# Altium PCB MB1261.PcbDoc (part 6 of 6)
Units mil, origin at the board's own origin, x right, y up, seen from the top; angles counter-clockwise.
Board outline 5119.1 x 2638.79 mil, 6 copper layers (TOP, L2_GND, L3_SIG, L4_VCC, L5_GND, BOTTOM), stack 61 mil thick; 336 components, 316 nets, 1358 pads, 871 vias.
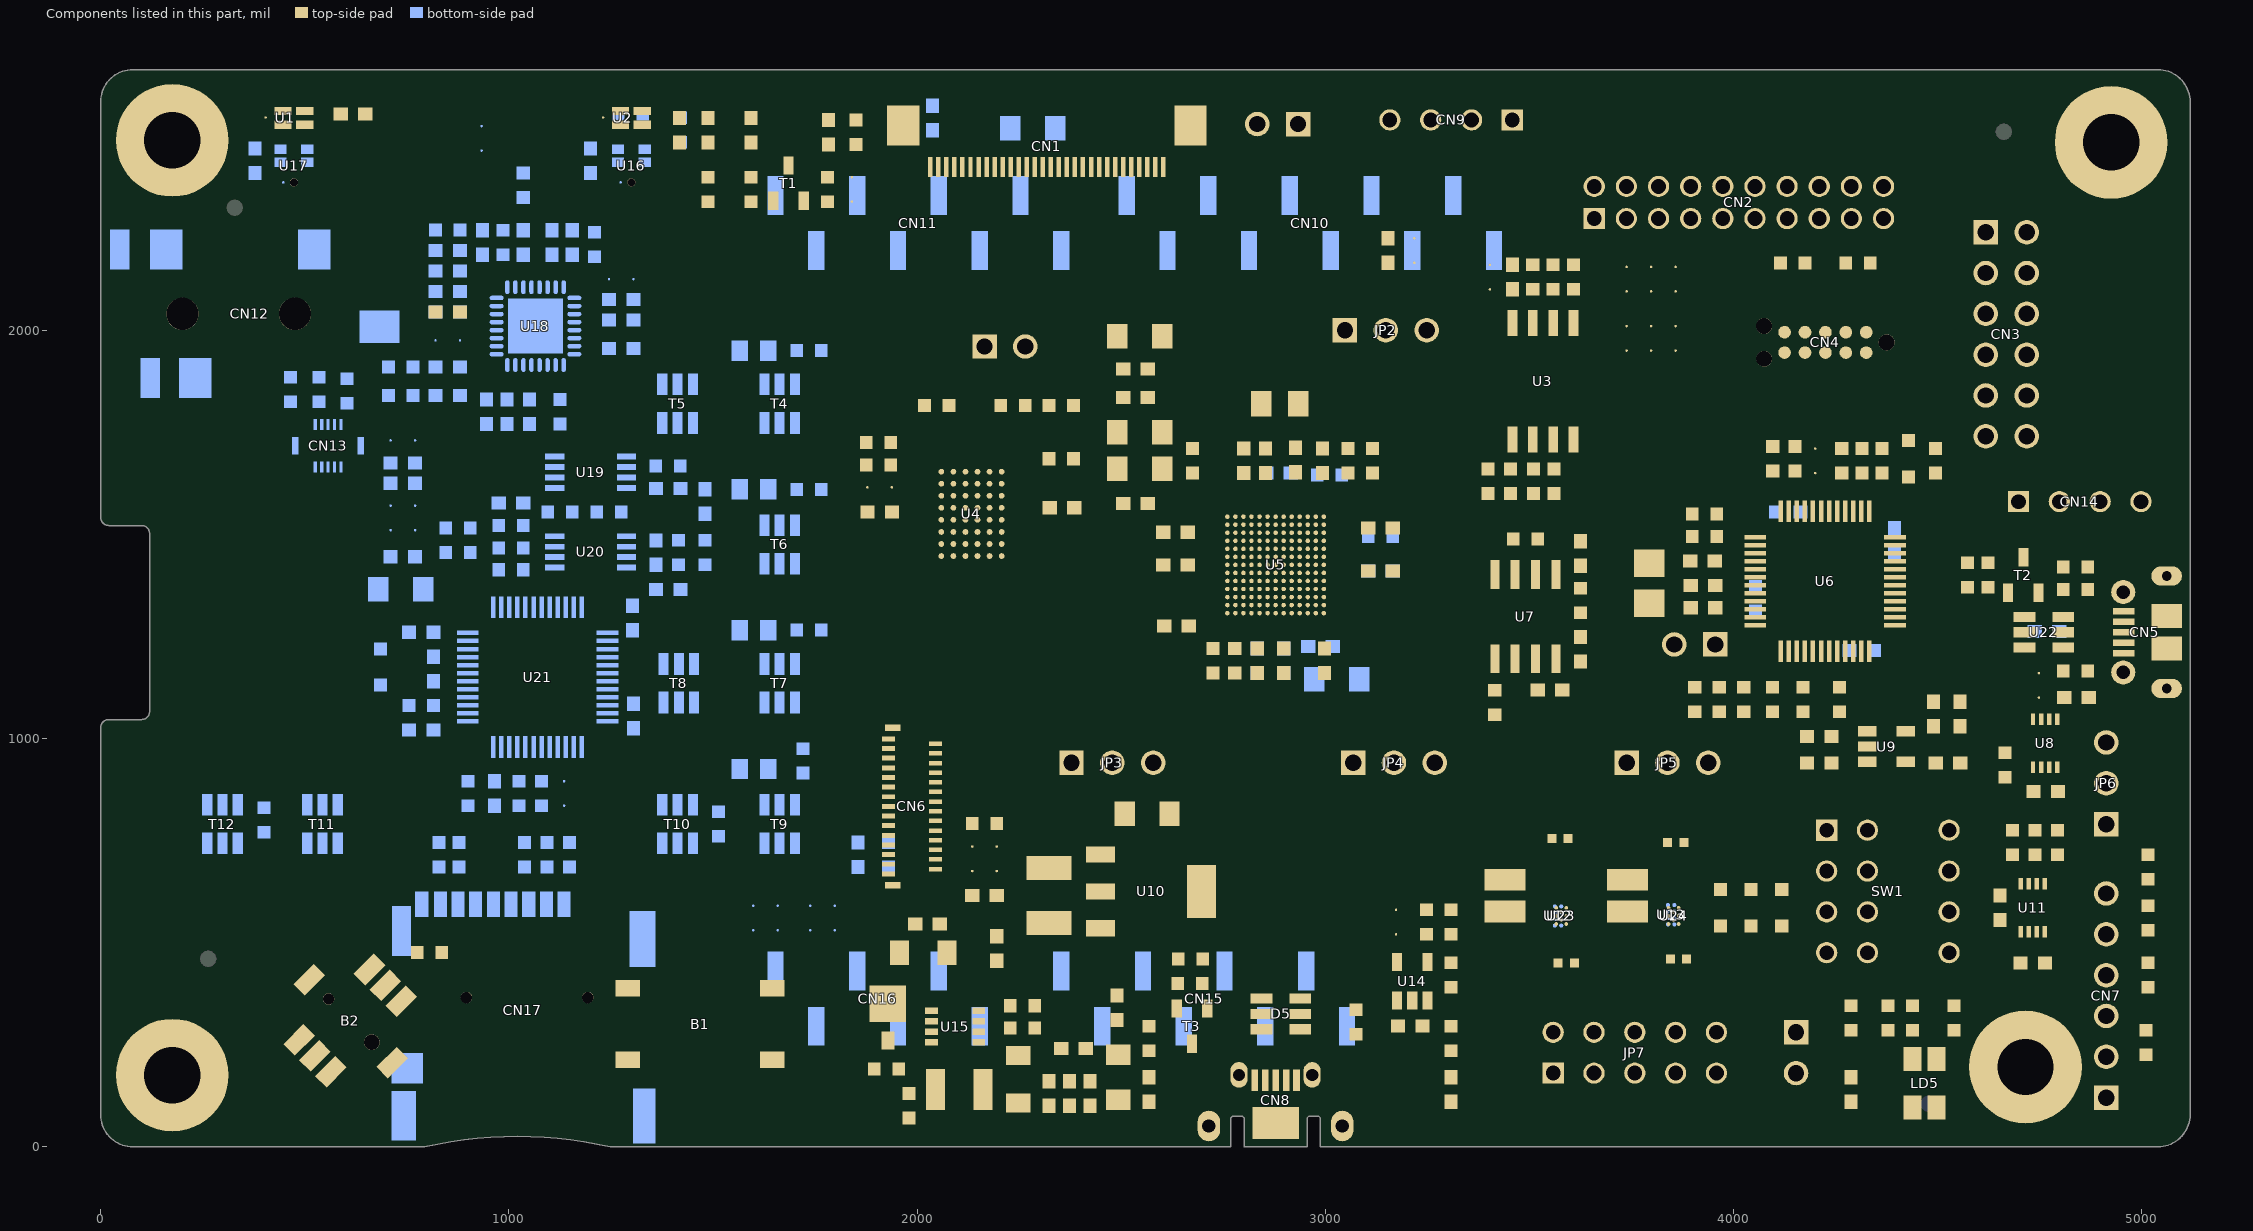
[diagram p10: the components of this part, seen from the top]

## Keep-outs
TOP:
  circle w1: c328.1,2300 r60
  circle w1: c328.1,2300 r65
  circle w1: c4662.1,2486 r60
  circle w1: c4662.1,2486 r65
  circle w1: c263.1,460 r65
  circle w1: c263.1,460 r60
  circle w1: c328.1,2300 r60
  circle w1: c328.1,2300 r65
  circle w1: c4662.1,2486 r60
  circle w1: c4662.1,2486 r65
  circle w1: c263.1,460 r65
  circle w1: c263.1,460 r60
BOTTOM:
  circle w1: c4478.1,105 r65
  circle w1: c4478.1,105 r60
  circle w1: c4662.1,2486 r65
  circle w1: c4662.1,2486 r60
  circle w1: c263.1,460 r60
  circle w1: c263.1,460 r65
  circle w1: c4478.1,105 r65
  circle w1: c4478.1,105 r60
  circle w1: c4662.1,2486 r65
  circle w1: c4662.1,2486 r60
  circle w1: c263.1,460 r60
  circle w1: c263.1,460 r65
Drill Drawing:
  lines w1: 0,78.74 ccw(c78.74,78.74) 78.74,0 ; 0,1025.71 cw(c20,1025.71) 20,1045.71 ; 0,1541.93 ccw(c20,1541.93) 20,1521.93 ; 0,2559.05 cw(c78.74,2559.05) 78.74,2637.79 ; 100,1045.71 ccw(c100,1065.71) 120,1065.71 ; 100,1521.93 cw(c100,1501.93) 120,1501.93 ; 793.1,0 cw(c1020.6,-1007.5) 1248.1,0 ; 5039.36,0 ccw(c5039.36,78.74) 5118.1,78.74 ; 5039.36,2637.79 cw(c5039.36,2559.05) 5118.1,2559.05

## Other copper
TOP:
  region net BLGND: 2124.6,254.63 2124.6,333.37 2113.77,333.37 2113.77,368.8 2098.02,368.8 2098.02,333.37 2088.18,333.37 2088.18,368.8 2072.43,368.8 2072.43,333.37 2061.6,333.37 2061.6,254.63 2072.43,254.63 2072.43,219.2 2088.18,219.2 2088.18,254.63 2098.02,254.63 2098.02,219.2 2113.77,219.2 2113.77,254.63 2124.6,254.63
  text "1" at 1474,106 h35
  text "B" at 1498,29 h35
  text "1" at 2685,-1790 h75
  text "1" at 2685,-1790 h75
  text "PRIMARY SIDE" at 2185,-1940 h60
  text "PRIMARY SIDE" at 2185,-1940 h60
BOTTOM:
  text "6" at 1848,107 h35
  text "6" at 1848,107 h35
  text "B" at 1848,26 h35
  text "B" at 1848,26 h35
  text "6" at 2635,-1790 h75
  text "6" at 2635,-1790 h75
  text "SECONDARY SIDE" at 2185,-1940 h60
  text "SECONDARY SIDE" at 2185,-1940 h60
Multi-Layer:
  pour cut-out: 1378,164 1948,164 1948,3 1378,3

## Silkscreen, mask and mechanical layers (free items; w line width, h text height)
Top Overlay:
  drawing of 5630 lines, arcs and shapes, not listed
  text "STMod+" at 3580,2410 h35 r90
  text "PMOD" at 4610,2340 h35
  text "Camera" at 2095,2305 h35
  text "www.st.com/stm32l4-discovery" at 408,2303 h40
  text "STM32L496G-DISCO" at 423,2162 h80
  text "MB1261B" at 1033.3,2084.3 h50
  text "IDD" at 2975,1900 h35
  text "VDD" at 3215,1900 h35
  text "TAG" at 3960,1855 h35 r90
  text "USB" at 4898.9,1493 h35
  text "STLINK" at 4895,1445 h35
  text "LCD" at 1919.59,1128.45 h35
  text "ARD_5V_OUT" at 2380,995 h35 r90
  text "ARD_5V_IN" at 2560,995 h35 r90
  text "VDD_SWD" at 5105,875 h35 r90
  text "+3V3" at 3645,845 h35
  text "+1V8" at 3885,840 h35
  text "+3V3" at 2985,835 h35
  text "VDD_MCU" at 3235,835 h35
  text "VDD_MCU" at 5105,635 h35 r90
  text "U" at 690,470 h50
  text "L" at 342,283 h50
  text "R" at 843,282 h50
  text "OTG FS" at 3049.1,133.9 h35
  text "D" at 480,115 h50
  text "S" at 1402,107 h35
  text "S" at 1402,107 h35
  text "COM" at 4380,80 h35 r90
  text "RESET" at 1133,49 h50
  text "JOYSTICK" at 390,45 h50
  text "B" at 1402,26 h35
  text "B" at 1402,26 h35
  text "SWD" at 5040,25 h35 r90
  text "E5V" at 3680,15 h35 r90
  text "U5V" at 3790,15 h35 r90
  text "ARD" at 3880,15 h35 r90
  text "STLK" at 3590,0 h35 r90
  text "CHGR" at 3980,0 h35 r90
  text "SILKSCREEN, (PRIMARY)" at 2185,-1940 h60
  text "SILKSCREEN, (PRIMARY)" at 2185,-1940 h60
Bottom Overlay:
  drawing of 467 lines, arcs and shapes, not listed
  text "D12" at 2855,2405 h35 r225
  text "GND" at 3045,2395 h35 r225
  text "D14" at 3250,2395 h35 r225
  text "D0" at 1635,2385 h35 r270
  text "D1" at 1735,2385 h35 r270
  text "D2" at 1835,2385 h35 r270
  text "D4" at 2035,2385 h35 r270
  text "D5" at 2130,2385 h35 r270
  text "D6" at 2235,2385 h35 r270
  text "D7" at 2340,2385 h35 r270
  text "D8" at 2495,2385 h35 r270
  text "D9" at 2595,2385 h35 r270
  text "D10" at 2695,2385 h35 r270
  text "D11" at 2800,2385 h35 r270
  text "D13" at 2985,2385 h35 r270
  text "D3" at 1944,2383 h35 r270
  text "D15" at 3390,2370 h35 r270
  text "AVDD" at 3190,2330 h35 r270
  text "Rev.B" at 3781,1925 h40 r270
  text "Audio Jack" at 340,1745 h35
  text "CTP" at 428.1,1615 h35
  text "MB1261" at 3776,1590 h50 r270
  text "GND" at 4830,1460 h35 r225
  text "+3V3" at 4588,1430 h35 r225
  text "SWDIO" at 4895,1415 h35 r225
  text "SWCLK" at 4680,1410 h35 r225
  text "SWO" at 5070,606 h35
  text "NRST" at 5097,499 h35
  text "SWDIO" at 5117,394 h35
  text "GND" at 5069,303 h35
  text "SWCLK" at 5120,198 h35
  text "5V" at 2635,180 h35 r270
  text "A5" at 1635,175 h35 r270
  text "A4" at 1730,175 h35 r270
  text "A3" at 1830,175 h35 r270
  text "A2" at 1935,175 h35 r270
  text "A1" at 2035,175 h35 r270
  text "A0" at 2130,175 h35 r270
  text "GND" at 2435,145 h35 r270
  text "GND" at 2535,145 h35 r270
  text "VIN" at 2330,140 h35 r270
  text "3V3" at 2720,140 h35 r270
  text "NRST" at 2843,120 h35 r270
  text "B" at 1919,106 h35
  text "B" at 1919,106 h35
  text "VDD" at 5070,98 h35
  text "IOREF" at 2900,90 h35 r270
  text "uSD" at 1400,36.9 h35 r270
  text "B" at 1919,25 h35
  text "B" at 1919,25 h35
  text "E5V" at 3645,15 h35 r270
  text "U5V" at 3752,15 h35 r270
  text "ARD" at 3845,15 h35 r270
  text "STLK" at 3555,0 h35 r270
  text "CHGR" at 3945,0 h35 r270
  text "SILKSCREEN, (SECONDARY)" at 3292,-1944 h60
  text "SILKSCREEN, (SECONDARY)" at 3292,-1944 h60
Top Paste:
  pour cut-out: 2124.6,254.63 2124.6,333.37 2113.77,333.37 2113.77,368.8 2098.02,368.8 2098.02,333.37 2088.18,333.37 2088.18,368.8 2072.43,368.8 2072.43,333.37 2061.6,333.37 2061.6,254.63 2072.43,254.63 2072.43,219.2 2088.18,219.2 2088.18,254.63 2098.02,254.63 2098.02,219.2 2113.77,219.2 2113.77,254.63 2124.6,254.63
  text "SOLDER PASTE (PRIMARY)" at 2185,-1940 h60
  text "SOLDER PASTE (PRIMARY)" at 2185,-1940 h60
Bottom Paste:
  text "SOLDER PASTE (SECONDARY)" at 2185,-1940 h60
  text "SOLDER PASTE (SECONDARY)" at 2185,-1940 h60
Top Solder:
  region: 1378,164 1948,164 1948,3 1378,3
  text "SOLDER MASK (PRIMARY)" at 2185,-1940 h60
  text "SOLDER MASK (PRIMARY)" at 2185,-1940 h60
Bottom Solder:
  text "SOLDER MASK (SECONDARY)" at 2185,-1940 h60
  text "SOLDER MASK (SECONDARY)" at 2185,-1940 h60
Mechanical 1:
  lines w1: 533.63,1615 582.03,1615 582.03,1671.2 533.63,1671.2 533.63,1615 ; 2005,1390 2260,1390 2260,1710 2005,1710 2005,1390 ; 2617.1,1305.4 2647.5,1275 2735,1275 2809.4,1275 2814.5,1269.9 2814.5,1223.8 2829.8,1208.5 2965.4,1208.5 2984,1227.1 2984,1269 2990,1275 3030,1275 3030,1320.1 3035.1,1325.2 3126.3,1325.2 3132,1330.9 3132,1512.7 3095.4,1549.3 3030,1549.3 3030,1570 2972,1570 2969.1,1572.9 2969.1,1593.3 2955.5,1606.9 2790.2,1606.9 2778.1,1594.8 2778.1,1570 2735,1570 2730,1565 2730,1525.9 2718.3,1514.2 2659.7,1514.2 2617.1,1471.6 2617.1,1305.4 ; 3525,530 3604.3,530 3604.3,594.3 3570,594.3 3554.3,610 3530,610 3525,605 3525,530 ; 3780,565 3809.7,535.3 3826.2,535.3 3878,535.3 3878,605 3820,605 3805,620 3790,620 3780,610 3780,565 ; 4384,1384 4444,1384 4444,1474 4384,1474 4384,1384 ; 4918.63,1185 4967.03,1185 4967.03,1241.2 4918.63,1241.2 4918.63,1185
LCD_MB1166:
  drawing of 462 lines, arcs and shapes, not listed
  text "10" at 1403.1,520.98 h25 r180
  text "20" at 1498.1,520.98 h25 r180
  text "30" at 1598.1,520.98 h25 r180
  text "40" at 1698.1,520.98 h25 r180
  text "50" at 1798.1,520.98 h25 r180
  text "60" at 1893.1,520.98 h25 r180
  text "2" at 1333.1,510.98 h25 r180
  text "25" at 851.46,279.35 h35 r180
  text "1" at 1070.46,274.35 h35 r180
  text "59" at 1898.1,115.98 h25 r180
  text "6" at 4142.29,-179.02 h35 r180
  text "1" at 4237.29,-179.02 h35 r180
DXF_MB1183:
  drawing of 442 lines, arcs and shapes, not listed
LAY4:
  lines w8: 1668,13 1728,13 ; 1668,13 1668,73 ; 1668,13 1728,13 ; 1668,13 1668,73 ; 1668,73 1678,73 ; 1668,73 1678,73 ; 1668,94 1728,94 ; 1668,94 1668,154 ; 1668,94 1728,94 ; 1668,94 1668,154 ; 1668,154 1678,154 ; 1668,154 1678,154 ; 1678,73 1728,73 ; 1678,73 1728,73 ; 1678,154 1728,154 ; 1678,154 1728,154 ; 1728,13 1728,73 ; 1728,13 1728,73 ; 1728,94 1728,154 ; 1728,94 1728,154
  text "4" at 1710,105 h35
  text "B" at 1684,25 h35
  text "B" at 1684,25 h35
  text "4" at 2685,-1790 h75
  text "4" at 2685,-1790 h75
  text "LAYER 4 (INTERNAL SIGNAL)" at 2185,-1940 h60
  text "LAYER 4 (INTERNAL SIGNAL)" at 2185,-1940 h60
DRAWING_ORIGIN:
  lines w1: -25,0 25,0 ; 0,-25 0,25
DIMENSION:
  drawing of 453 lines, arcs and shapes, not listed
  text "4.9mm" at 4387.92,3017.58 h85
  text "4.9mm" at 4387.92,3017.58 h85
  text "4.39mm" at -637.33,2977.85 h85
  text "4.39mm" at -637.33,2977.85 h85
  text "4.52mm" at 5199.05,2847.1 h85
  text "4.52mm" at 5199.05,2847.1 h85
  text "43.31mm" at 3931.75,2788.14 h85
  text "43.31mm" at 3931.75,2788.14 h85
  text "4.45mm" at 486.27,2750.89 h85
  text "4.45mm" at 486.27,2750.89 h85
  text "4.06mm" at 2807.92,2749.64 h85
  text "4.06mm" at 2807.92,2749.64 h85
  text "4XR2mm" at 5495.91,2671.07 h85
  text "4XR2mm" at 5495.91,2671.07 h85
  text "12.1mm" at -467.82,1246.88 h85
  text "12.1mm" at -467.82,1246.88 h85
  text "48.26mm" at 5226.57,1246.87 h85
  text "48.26mm" at 5226.57,1246.87 h85
  text "57.53mm" at 5848.2,1240.11 h85
  text "57.53mm" at 5848.2,1240.11 h85
  text "67mm" at -939.38,1205.63 h85 r90
  text "67mm" at -939.38,1205.63 h85 r90
  text "58.1mm" at -623.18,1143.76 h85 r90
  text "58.1mm" at -623.18,1143.76 h85 r90
  text "4.45mm" at -476.1,382.1 h85
  text "4.45mm" at -476.1,382.1 h85
  text "4.95mm" at 5655.47,38.21 h85
  text "4.95mm" at 5655.47,38.21 h85
  text "5.08mm" at 1377.14,-116.93 h85
  text "5.08mm" at 1377.14,-116.93 h85
  text "52.45mm" at 3802.28,-144.43 h85
  text "52.45mm" at 3802.28,-144.43 h85
  text "4.45mm" at -624.57,-248.21 h85
  text "4.45mm" at -624.57,-248.21 h85
  text "115.82mm" at 2341.72,-272.16 h85
  text "115.82mm" at 2341.72,-272.16 h85
  text "9.73mm" at 5373.28,-272.16 h85
  text "9.73mm" at 5373.28,-272.16 h85
  text "130mm" at 2472.23,-414.6 h85
  text "130mm" at 2472.23,-414.6 h85
  text "FAB DARWING & DRILL LEGEND" at 2185,-1940 h60
  text "FAB DARWING & DRILL LEGEND" at 2185,-1940 h60
LAY5:
  lines w8: 1738,13 1798,13 ; 1738,13 1738,73 ; 1738,13 1798,13 ; 1738,13 1738,73 ; 1738,73 1748,73 ; 1738,73 1748,73 ; 1738,94 1798,94 ; 1738,94 1738,154 ; 1738,94 1798,94 ; 1738,94 1738,154 ; 1738,154 1748,154 ; 1738,154 1748,154 ; 1748,73 1798,73 ; 1748,73 1798,73 ; 1748,154 1798,154 ; 1748,154 1798,154 ; 1798,13 1798,73 ; 1798,13 1798,73 ; 1798,94 1798,154 ; 1798,94 1798,154
  text "5" at 1778,107 h35
  text "5" at 1778,107 h35
  text "B" at 1778,26 h35
  text "B" at 1778,26 h35
  text "5" at 2685,-1790 h75
  text "5" at 2685,-1790 h75
  text "LAYER 5 (GND PLANE)" at 2185,-1940 h60
  text "LAYER 5 (GND PLANE)" at 2185,-1940 h60
LAY3:
  lines w8: 1598,13 1658,13 ; 1598,13 1598,73 ; 1598,13 1658,13 ; 1598,13 1598,73 ; 1598,73 1608,73 ; 1598,73 1608,73 ; 1598,94 1658,94 ; 1598,94 1598,154 ; 1598,94 1658,94 ; 1598,94 1598,154 ; 1598,154 1608,154 ; 1598,154 1608,154 ; 1608,73 1658,73 ; 1608,73 1658,73 ; 1608,154 1658,154 ; 1608,154 1658,154 ; 1658,13 1658,73 ; 1658,13 1658,73 ; 1658,94 1658,154 ; 1658,94 1658,154
  text "3" at 1612,105 h35
  text "3" at 1612,105 h35
  text "B" at 1612,24 h35
  text "B" at 1612,24 h35
  text "3" at 2685,-1790 h75
  text "3" at 2685,-1790 h75
  text "LAYER 3 (VTT PLANE)" at 2185,-1940 h60
  text "LAYER 3 (VTT PLANE)" at 2185,-1940 h60
Drill Drawing:
  drawing of 25598 lines, arcs and shapes, not listed
  text "6" at -1460,10960 h130
  text "5" at 2040,10960 h130
  text "4" at 5540,10960 h130
  text "3" at 9040,10960 h130
  text "2" at 12540,10960 h130
  text "1" at 16040,10960 h130
  text "REVISIONS" at 15140,10710 h85
  text "REV" at 13690,10460 h75
  text "DESCRIPTION" at 14240,10460 h75
  text "DATE" at 16390,10460 h75
  text "APPROVED" at 17090,10460 h75
  text "1.0" at 13690,10260 h75
  text "EDITION ORIGINALE" at 14240,10260 h75
  text "2008-**-**" at 16240,10260 h75
  text "***" at 17250,10260 h75
  text "D" at -3460,8660 h130
  text "D" at 17840,8660 h130
  text "5" at 11880,7908 h100
  text "IMPEDANCE TABLE" at 12110.81,7881.53 h100
  text "LAYER" at 12035.81,7587.53 h75
  text "TOLERANCE" at 15785.81,7587.53 h75
  text "TRACE" at 12785.81,7577.53 h75
  text "SPACEING" at 13335.81,7577.53 h75
  text "IMPEDANCE" at 14085.81,7577.53 h75
  text "IMPEDANCE" at 14985.81,7577.53 h75
  text "(mil)" at 12835.81,7487.53 h50
  text "(Single end)" at 14135.81,7487.53 h50
  text "(mil)" at 13435.81,7477.53 h50
  text "(Differential)" at 14985.81,7477.53 h50
  text "1,6" at 12030.81,7341.53 h75
  text "5.0" at 12830.81,7331.53 h75
  text "N/A" at 13485.81,7277.53 h75
  text "55 OHM" at 14135.81,7267.53 h75
  text "N/A" at 15135.81,7267.53 h75
  text "+/-10%" at 15885.81,7267.53 h75
  text "4.0" at 12820.81,7211.53 h75
  text "4" at 12030.81,7201.53 h75
  text "N/A" at 14240.81,7031.53 h75
  text "1,6" at 11998.81,7029.53 h75
  text "10.2" at 13434.81,7029.53 h75
  text "90 OHM" at 15052.81,7029.53 h75
  text "+/-10%" at 15885.81,7017.53 h75
  text "4.8" at 12828.81,7015.53 h75
  text "100 OHM" at 15027.81,6773.53 h75
  text "+/-10%" at 15891.81,6773.53 h75
  text "N/A" at 14245.81,6752.53 h75
  text "Symbol" at 110.54,6751.43 h118.11
  text "Hit Count" at 573.2,6751.43 h118.11
  text "Finished Hole Size" at 1126.69,6751.43 h118.11
  text "Plated" at 2117.6,6751.43 h118.11
  text "Tolerance" at 2523.76,6751.43 h118.11
  text "Hole Type" at 3109.38,6751.43 h118.11
  text "Hole Length" at 3700.69,6751.43 h118.11
  text "Rotation" at 4377.36,6751.43 h118.11
  text "Drill Layer Pair" at 4877.84,6751.43 h118.11
  text "2" at 767.89,6547.59 h98.43
  text "24.00mil" at 1398.79,6547.59 h98.43
  text "PTH" at 2178.4,6547.59 h98.43
  text "+5.0/-5.0" at 2584.74,6547.59 h98.43
  text "Slot" at 3270.37,6547.59 h98.43
  text "51.00mil" at 3816.22,6547.59 h98.43
  text "0" at 4545.86,6547.59 h98.43
  text "TOP - BOTTOM" at 4877.84,6547.59 h98.43
  text "2" at 767.89,6343.75 h98.43
  text "30.00mil" at 1399.39,6343.75 h98.43
  text "PTH" at 2178.4,6343.75 h98.43
  text "+5.0/-5.0" at 2584.74,6343.75 h98.43
  text "Slot" at 3270.37,6343.75 h98.43
  text "33.00mil" at 3816.26,6343.75 h98.43
  text "90" at 4521.35,6343.75 h98.43
  text "TOP - BOTTOM" at 4877.84,6343.75 h98.43
  text "2" at 767.89,6139.92 h98.43
  text "33.00mil" at 1399.39,6139.92 h98.43
  text "PTH" at 2178.4,6139.92 h98.43
  text "+5.0/-5.0" at 2584.74,6139.92 h98.43
  text "Slot" at 3270.37,6139.92 h98.43
  text "59.00mil" at 3816.22,6139.92 h98.43
  text "90" at 4521.35,6139.92 h98.43
  text "TOP - BOTTOM" at 4877.84,6139.92 h98.43
  text "Symbol" at 6723.7,5971.75 h118.11
  text "Hit Count" at 7186.36,5971.75 h118.11
  text "Finished Hole Size" at 7739.85,5971.75 h118.11
  text "Plated" at 8730.76,5971.75 h118.11
  text "Tolerance" at 9136.92,5971.75 h118.11
  text "Hole Type" at 9722.54,5971.75 h118.11
  text "Rotation" at 10313.85,5971.75 h118.11
  text "Drill Layer Pair" at 10814.33,5971.75 h118.11
  text "43" at 742.29,5936.08 h98.43
  text "8.00mil" at 1423.8,5936.08 h98.43
  text "PTH" at 2178.4,5936.08 h98.43
  text "+3.0/-3.0" at 2584.74,5936.08 h98.43
  text "Round" at 3220.76,5936.08 h98.43
  text "-" at 3965.89,5936.08 h98.43
  text "TOP - BOTTOM" at 4877.84,5936.08 h98.43
  text "63" at 7356.59,5767.92 h98.43
  text "4.00mil" at 8035.68,5767.92 h98.43
  text "PTH" at 8791.56,5767.92 h98.43
  text "+3.0/-3.0" at 9197.9,5767.92 h98.43
  text "Round" at 9833.92,5767.92 h98.43
  text "TOP - L3_SIG" at 10882.23,5767.92 h98.43
  text "317" at 719.15,5732.25 h98.43
  text "10.00mil" at 1402.3,5732.25 h98.43
  text "PTH" at 2178.4,5732.25 h98.43
  text "+3.0/-3.0" at 2584.74,5732.25 h98.43
  text "Round" at 3220.76,5732.25 h98.43
  text "-" at 3965.89,5732.25 h98.43
  text "TOP - BOTTOM" at 4877.84,5732.25 h98.43
  text "4" at 12782.38,5634.07 h75
  text "LAYER STACK-UP" at 12982.38,5634.07 h75
  text "63 Total" at 7247.45,5564.08 h98.43
  text "289" at 718.51,5528.41 h98.43
  text "12.00mil" at 1402.3,5528.41 h98.43
  text "PTH" at 2178.4,5528.41 h98.43
  text "+3.0/-3.0" at 2584.74,5528.41 h98.43
  text "Round" at 3220.76,5528.41 h98.43
  text "-" at 3965.89,5528.41 h98.43
  text "TOP - BOTTOM" at 4877.84,5528.41 h98.43
  text "SOLDERMASK & SILKSCREEN" at 14732.38,5504.07 h60
  text "Symbol" at 6735.55,5400.75 h118.11
  text "Hit Count" at 7198.21,5400.75 h118.11
  text "Finished Hole Size" at 7751.7,5400.75 h118.11
  text "Plated" at 8742.61,5400.75 h118.11
  text "Tolerance" at 9148.76,5400.75 h118.11
  text "Hole Type" at 9734.38,5400.75 h118.11
  text "Rotation" at 10325.69,5400.75 h118.11
  text "Drill Layer Pair" at 10826.17,5400.75 h118.11
  text "TOP     (1/3 oz cu+plating)" at 14722.38,5384.07 h60
  text "2" at 767.89,5324.57 h98.43
  text "20.00mil" at 1398.79,5324.57 h98.43
  text "PTH" at 2178.4,5324.57 h98.43
  text "+3.0/-3.0" at 2584.74,5324.57 h98.43
  text "Round" at 3220.76,5324.57 h98.43
  text "-" at 3965.89,5324.57 h98.43
  text "TOP - BOTTOM" at 4877.84,5324.57 h98.43
  text "PREPREG  2.8 mil" at 13622.38,5209.07 h60
  text "52" at 7368.94,5196.92 h98.43
  text "8.00mil" at 8048.8,5196.92 h98.43
  text "PTH" at 8803.41,5196.92 h98.43
  text "+3.0/-3.0" at 9209.75,5196.92 h98.43
  text "Round" at 9845.77,5196.92 h98.43
  text "L2_GND - L5_GND" at 10826.17,5196.92 h98.43
  text "2" at 767.89,5120.74 h98.43
  text "33.00mil" at 1399.39,5120.74 h98.43
  text "PTH" at 2178.4,5120.74 h98.43
  text "+3.0/-3.0" at 2584.74,5120.74 h98.43
  text "Round" at 3220.76,5120.74 h98.43
  text "-" at 3965.89,5120.74 h98.43
  text "TOP - BOTTOM" at 4877.84,5120.74 h98.43
  text "LAYER 2 ( 1/3 oz cu+plating)" at 14722.38,5084.07 h60
  text "52 Total" at 7259.48,4993.08 h98.43
  text "50" at 743.7,4916.9 h98.43
  text "36.00mil" at 1399.39,4916.9 h98.43
  text "PTH" at 2178.4,4916.9 h98.43
  text "+3.0/-3.0" at 2584.74,4916.9 h98.43
  text "Round" at 3220.76,4916.9 h98.43
  text "-" at 3965.89,4916.9 h98.43
  text "TOP - BOTTOM" at 4877.84,4916.9 h98.43
  text "PREPREG  4.0 mil" at 13622.38,4909.07 h60
  text "PREPREG  4.0 mil" at 13622.38,4909.07 h60
  text "Symbol" at 6746.48,4816.75 h118.11
  text "Hit Count" at 7209.14,4816.75 h118.11
  text "Finished Hole Size" at 7762.63,4816.75 h118.11
  text "Plated" at 8753.54,4816.75 h118.11
  text "Tolerance" at 9159.69,4816.75 h118.11
  text "Hole Type" at 9745.32,4816.75 h118.11
  text "Rotation" at 10336.63,4816.75 h118.11
  text "Drill Layer Pair" at 10837.1,4816.75 h118.11
  text "LAYER 3 (0.5 oz)" at 14722.38,4784.07 h60
  text "C" at -3460,4760 h130
  text "C" at 17840,4760 h130
  text "1.2 mm" at 12550.38,4751.57 h75
  text "41" at 748.39,4713.07 h98.43
  text "40.00mil" at 1398.02,4713.07 h98.43
  text "PTH" at 2178.4,4713.07 h98.43
  text "+3.0/-3.0" at 2584.74,4713.07 h98.43
  text "Round" at 3220.76,4713.07 h98.43
  text "-" at 3965.89,4713.07 h98.43
  text "TOP - BOTTOM" at 4877.84,4713.07 h98.43
  text "CORE     **.*mil" at 13622.38,4674.07 h60
  text "+/-10%" at 12592.38,4644.07 h50
  text "31" at 7385.7,4612.92 h98.43
  text "4.00mil" at 8058.46,4612.92 h98.43
  text "PTH" at 8814.34,4612.92 h98.43
  text "+3.0/-3.0" at 9220.68,4612.92 h98.43
  text "Round" at 9856.7,4612.92 h98.43
  text "L5_GND - BOTTOM" at 10837.1,4612.92 h98.43
  text "LAYER 4 (0.5 oz)" at 14722.38,4584.07 h60
  text "4" at 766.93,4509.23 h98.43
  text "138.00mil" at 1377.79,4509.23 h98.43
  text "PTH" at 2178.4,4509.23 h98.43
  text "+3.0/-3.0" at 2584.74,4509.23 h98.43
  text "Round" at 3220.76,4509.23 h98.43
  text "-" at 3965.89,4509.23 h98.43
  text "TOP - BOTTOM" at 4877.84,4509.23 h98.43
  text "31 Total" at 7270.46,4409.08 h98.43
  text "PREPREG  4.0 mil" at 13622.38,4409.07 h60
  text "3" at 768.16,4305.39 h98.43
  text "28.00mil" at 1398.79,4305.39 h98.43
  text "NPTH" at 2146.56,4305.39 h98.43
  text "+2.0/-2.0" at 2584.74,4305.39 h98.43
  text "Round" at 3220.76,4305.39 h98.43
  text "-" at 3965.89,4305.39 h98.43
  text "TOP - BOTTOM" at 4877.84,4305.39 h98.43
  text "LAYER 5 ( 1/3 oz cu+plating)" at 14722.38,4284.07 h60
  text "Symbol" at 6736.7,4228.68 h118.11
  text "Hit Count" at 7199.36,4228.68 h118.11
  text "Finished Hole Size" at 7752.85,4228.68 h118.11
  text "Plated" at 8743.76,4228.68 h118.11
  text "Tolerance" at 9149.92,4228.68 h118.11
  text "Hole Type" at 9735.54,4228.68 h118.11
  text "Rotation" at 10326.85,4228.68 h118.11
  text "Drill Layer Pair" at 10827.33,4228.68 h118.11
  text "PREPREG  2.8 mil" at 13622.38,4109.07 h60
  text "4" at 766.93,4101.56 h98.43
  text "39.00mil" at 1399.39,4101.56 h98.43
  text "NPTH" at 2146.56,4101.56 h98.43
  text "+2.0/-2.0" at 2584.74,4101.56 h98.43
  text "Round" at 3220.76,4101.56 h98.43
  text "-" at 3965.89,4101.56 h98.43
  text "TOP - BOTTOM" at 4877.84,4101.56 h98.43
  text "76" at 7370.04,4024.85 h98.43
  text "4.00mil" at 8048.68,4024.85 h98.43
  text "PTH" at 8804.56,4024.85 h98.43
  text "+3.0/-3.0" at 9210.9,4024.85 h98.43
  text "Round" at 9846.92,4024.85 h98.43
  text "TOP - L2_GND" at 10872.87,4024.85 h98.43
  text "BOTTOM  (1/3 oz cu+plating)" at 14722.38,3984.07 h60
  text "2" at 767.89,3897.72 h98.43
  text "79.00mil" at 1399.61,3897.72 h98.43
  text "NPTH" at 2146.56,3897.72 h98.43
  text "+2.0/-2.0" at 2584.74,3897.72 h98.43
  text "Round" at 3220.76,3897.72 h98.43
  text "-" at 3965.89,3897.72 h98.43
  text "TOP - BOTTOM" at 4877.84,3897.72 h98.43
  text "SOLDERMASK & SILKSCREEN" at 14722.38,3854.07 h60
  text "76 Total" at 7260.91,3821.01 h98.43
  text "763 Total" at 610.24,3693.89 h98.43
  text "6 LAYER STACKING" at 13362.38,3674.07 h75
  text "Slot definitions :" at 110.54,3551.2 h98.43
  text "Routed Path Length" at 782.24,3551.2 h98.43
  text "= Calculated from tool start centre position to tool end centre position." at 1614.37,3551.2 h98.43
  text "HDI 1+4+1" at 13582.38,3494.07 h75
  text "Hole Length" at 782.24,3469.67 h98.43
  text "= Routed Path Length + Tool Size = Slot length as defined in the PCB layout" at 1305.45,3469.67 h98.43
  text "PCB SPECIFICATIONS:" at 11656,2676 h85
  text "A. MATERIAL;" at 11656,2476 h85
  text "FR-4," at 13406,2476 h85
  text "TG-170" at 14356,2476 h85
  text "TG-150" at 15106,2476 h85
  text "TG-140" at 15956,2476 h85
  text "B. MATERIAL FAMILY;" at 11656,2276 h85
  text "N/A." at 13406,2276 h85
  text "C. SOLDERMASK COLOR;" at 11656,2076 h85
  text "GREEN" at 13556,2076 h85
  text "BLUE" at 14306,2076 h85
  text "RED" at 15156,2076 h85
  text "BLACK" at 16006,2076 h85
  text "D. SILKSCREEN COLOR;" at 11656,1876 h85
  text "WHITE" at 13556,1876 h85
  text "YELLOW" at 14306,1876 h85
  text "BLACK" at 15156,1876 h85
  text "E. SURFACE FINISH;" at 11656,1676 h85
  text "ENIG" at 13556,1676 h85
  text "IMMERSION SILVER" at 14306,1676 h85
  text "IMMERSION TIN" at 16006,1676 h85
  text "HASL" at 13556,1476 h85
  text "HASL(PB-FREE)" at 14306,1476 h85
  text "GOLDEN FINGER" at 16006,1476 h85
  text "NO" at 13556,1276 h85
  text "YES" at 14306,1276 h85
  text "(SEE IMPEDANCE TABLE FOR DETAIL INFORMATION)" at 14506,1276 h85
  text "F. IMPEDANCE CONTROL;" at 11745,1269 h85
  text "G. THROUGH VIA;" at 11656,1076 h85
  text "PLUG THE VIAS WHICH ARE COVERED WITH SOLDERMASK ONE OR TWO SIDE." at 13106,1076 h85
  text "B" at 17840,1060 h130
  text "B" at -3460,1047 h130
  text "PLUG MATERIAL:" at 13106,876 h85
  text "SOLDERMASK" at 14706,876 h85
  text "NON-CONDUCTIVE EPOXY." at 16006,876 h85
  text "SEE LAYER STACK-UP SEQUENCE FOR OVERALL THICKNESS." at 13106,676 h85
  text "H. STACK-UP;" at 11749,656 h85
  text "PCB REQUIREMENTS:" at 11646,376 h85
  text "1. THIS BOARD WILL CONFORM TO:" at 11596,176 h85
  text "IPC-A-600. CURRENT REV., CLASS II" at 11596,26 h85
  text "IPC-6012, CURRENT REV., CLASS II" at 11596,-124 h85
  text "2. UNLESS OTHERWISE SPECIFIED ALL HOLE DIMENSIONS APPLY AFTER PLATING." at 11596,-334 h85
  text "ALL HOLES SHALL BE LOCATED WITHIN .003\" DIAMETER OF TRUE POSITION." at 11596,-484 h85
  text "3. PLATED HOLE WALL THICKNESS SHALL NOT BE LESS THAN .001 INCH MINIMUM" at 11596,-684 h85
  text "AVERAGE, WITH NO READING LESS THAN .0008 BY COROSS SECTION." at 11776,-824 h85
  text "4. MATERIAL FR4 RATING 94V-0 MINIMUM EPOXY GLASS LAMINATE." at 11596,-1034 h85
  text "5. BOARD SHALL BE LPI SOLDER MASKED OVER BARE COPPER BOTH SIDES PER" at 11596,-1214 h85
  text "IPC-SM-840 CLASS II." at 11596,-1364 h85
  text "6. SILKSCREEN SHALL BE PERMANENT NON-CONDUCTIVE INK AND WITH NO OVERLAP" at 11596,-1564 h85
  text "ON ANY COMPONENT PAD OR THROUGH HOLE." at 11596,-1714 h85
  text "COMPANY NAME:" at 3735,-1740 h60
  text "LAYER:" at 2135,-1790 h75
  text "ST" at 3885,-1890 h75
  text "7. MFGR, TO LEGIBLY ETCH OR STAMP/SCREEN WITH PERMANENT NON-CONDUCTIVE INK" at 11596,-1914 h85
  text "PROJECT NAME:" at 3735,-2040 h60
  text "D. MFGR. LOGO" at 13446,-2044 h85
  text "DESIGNED BY SOFER" at 865,-2060 h60
  text "A. U.L. CODE" at 11886,-2064 h85
  text "www.sofer.com.cn" at 885,-2160 h60
  text "E. SUCCESSFUL ELECTRICAL BOARD TEST." at 13446,-2184 h85
  text "MB1261" at 3892,-2187 h75
  text "DESIGNER:" at 2185,-2190 h60
  text "Shelley" at 2685,-2190 h60
  text "B. DATE CODE" at 11886,-2204 h85
  text "Tel : +86 21 - 6482 6908" at 685,-2340 h60
  text "PROJECT NUMBER:" at 3735,-2340 h60
  text "REV" at 4935,-2340 h60
  text "C. FLAMMABILITY RATING" at 11886,-2344 h85
  text "Mail: design@sofer.com.cn" at 685,-2440 h60
  text "DATE:" at 2185,-2440 h60
  text "2016.09.30" at 2485,-2440 h60
  text "D031-023A2" at 3885,-2490 h75
  text "B" at 5035,-2490 h75
  text "8. REMOVE THE FLASHS WHICH SMALLER THAN HOLE SIZE." at 11596,-2554 h85
  text "9. REMOVE ALL SHAPE EDGES AND BURRS .005 MAXIMUM." at 11596,-2754 h85
  text "10. PLEASE USE THE SUPPLIED IPC 356 NETLIST TO VERIFY BOARD BEFORE" at 11596,-2964 h85
  text "FABRICATING BOARD." at 11596,-3114 h85
  text "A" at -3460,-3140 h130
  text "A" at 17840,-3140 h130
  text "UNLESS OTHERWISE SPECIFIED" at 10590,-3440 h75
  text "SIGNATURES" at 12490,-3490 h75
  text "DATE" at 13890,-3490 h75
  text "DATE" at 13890,-3490 h75
  text "LOGO" at 14590,-3640 h130
  text "COMPANY NAME" at 16090,-3640 h130
  text "YY-MM-DD" at 13789,-3688 h75
  text "DRAWN" at 12490,-3690 h75
  text "DIMENSIONS ARE IN INCHES" at 10640,-3740 h75
  text "TOLERANCES ON;" at 10640,-3890 h75
  text "CHECKED" at 12490,-3890 h75
  text "YY-MM-DD" at 13790,-3890 h75
  text "2 PL DECIMALS +" at 10640,-4040 h75
  text "TITLE" at 14490,-4040 h100
  text "ENGRG" at 12490,-4090 h75
  text "YY-MM-DD" at 13790,-4090 h75
  text "PROJECT NAME *" at 15240,-4140 h130
  text "3 PL DECIMALS +" at 10640,-4190 h75
  text "ISSUED" at 12490,-4290 h75
  text "ANGLES +" at 10640,-4340 h75
  text "SIZE" at 14515,-4415 h75
  text "B" at 14915,-4415 h75
  text "DWG NO" at 15265,-4415 h75
  text "*********" at 15865,-4415 h75
  text "REV" at 17165,-4415 h75
  text "**" at 17465,-4415 h75
  text "FRACTIONS +" at 10640,-4490 h75
  text "SCALE" at 14515,-4665 h75
  text "1:1" at 14915,-4665 h75
  text "SHEET" at 16515,-4665 h75
  text "1 OF 1" at 17115,-4665 h75
  text "2" at 12535,-4939 h130
  text "6" at -1460,-4940 h130
  text "5" at 2040,-4940 h130
  text "1" at 16040,-4940 h130
  text "3" at 9026,-4943 h130
  text "4" at 5532,-4946 h130
LAY2:
  lines w8: 1528,13 1588,13 ; 1528,13 1528,73 ; 1528,13 1588,13 ; 1528,13 1528,73 ; 1528,73 1538,73 ; 1528,73 1538,73 ; 1528,94 1588,94 ; 1528,94 1528,154 ; 1528,94 1588,94 ; 1528,94 1528,154 ; 1528,154 1538,154 ; 1528,154 1538,154 ; 1538,73 1588,73 ; 1538,73 1588,73 ; 1538,154 1588,154 ; 1538,154 1588,154 ; 1588,13 1588,73 ; 1588,13 1588,73 ; 1588,94 1588,154 ; 1588,94 1588,154
  text "2" at 1546,106 h35
  text "2" at 1546,106 h35
  text "B" at 1546,25 h35
  text "B" at 1546,25 h35
  text "2" at 2685,-1790 h75
  text "2" at 2685,-1790 h75
  text "LAYER 2 (GND PLANE)" at 2185,-1940 h60
  text "LAYER 2 (GND PLANE)" at 2185,-1940 h60
REVISION_BLOCK:
  lines w1: 13590,9610 13590,10860 13590,9610 ; 13590,9810 17740,9810 13590,9810 ; 13590,10010 17740,10010 13590,10010 ; 13590,10210 17740,10210 13590,10210 ; 13590,10410 17740,10410 13590,10410 ; 13590,10610 17740,10610 13590,10610 ; 13990,9610 13990,10610 13990,9610 ; 16190,9610 16190,10610 16190,9610 ; 16940,9610 16940,10610 16940,9610
REVISION_DATA:
  text "REVISIONS" at 15140,10710 h85
  text "REVISIONS" at 15140,10710 h85
  text "REV" at 13690,10460 h75
  text "REV" at 13690,10460 h75
  text "DESCRIPTION" at 14240,10460 h75
  text "DESCRIPTION" at 14240,10460 h75
  text "DATE" at 16390,10460 h75
  text "DATE" at 16390,10460 h75
  text "APPROVED" at 17090,10460 h75
  text "APPROVED" at 17090,10460 h75
  text "1.0" at 13690,10260 h75
  text "1.0" at 13690,10260 h75
  text "EDITION ORIGINALE" at 14240,10260 h75
  text "EDITION ORIGINALE" at 14240,10260 h75
  text "2008-**-**" at 16240,10260 h75
  text "2008-**-**" at 16240,10260 h75
  text "***" at 17250,10260 h75
  text "***" at 17250,10260 h75
TITLE_DATA:
  text "UNLESS OTHERWISE SPECIFIED" at 10590,-3440 h75
  text "UNLESS OTHERWISE SPECIFIED" at 10590,-3440 h75
  text "SIGNATURES" at 12490,-3490 h75
  text "SIGNATURES" at 12490,-3490 h75
  text "DATE" at 13890,-3490 h75
  text "DATE" at 13890,-3490 h75
  text "LOGO" at 14590,-3640 h130
  text "LOGO" at 14590,-3640 h130
  text "COMPANY NAME" at 16090,-3640 h130
  text "COMPANY NAME" at 16090,-3640 h130
  text "DRAWN" at 12490,-3690 h75
  text "DRAWN" at 12490,-3690 h75
  text "YY-MM-DD" at 13790,-3690 h75
  text "YY-MM-DD" at 13790,-3690 h75
  text "DIMENSIONS ARE IN INCHES" at 10640,-3740 h75
  text "DIMENSIONS ARE IN INCHES" at 10640,-3740 h75
  text "TOLERANCES ON;" at 10640,-3890 h75
  text "TOLERANCES ON;" at 10640,-3890 h75
  text "CHECKED" at 12490,-3890 h75
  text "CHECKED" at 12490,-3890 h75
  text "YY-MM-DD" at 13790,-3890 h75
  text "YY-MM-DD" at 13790,-3890 h75
  text "2 PL DECIMALS +" at 10640,-4040 h75
  text "2 PL DECIMALS +" at 10640,-4040 h75
  text "TITLE" at 14490,-4040 h100
  text "TITLE" at 14490,-4040 h100
  text "ENGRG" at 12490,-4090 h75
  text "ENGRG" at 12490,-4090 h75
  text "YY-MM-DD" at 13790,-4090 h75
  text "YY-MM-DD" at 13790,-4090 h75
  text "PROJECT NAME *" at 15240,-4140 h130
  text "PROJECT NAME *" at 15240,-4140 h130
  text "3 PL DECIMALS +" at 10640,-4190 h75
  text "3 PL DECIMALS +" at 10640,-4190 h75
  text "ISSUED" at 12490,-4290 h75
  text "ISSUED" at 12490,-4290 h75
  text "ANGLES +" at 10640,-4340 h75
  text "ANGLES +" at 10640,-4340 h75
  text "SIZE" at 14515,-4415 h75
  text "SIZE" at 14515,-4415 h75
  text "B" at 14915,-4415 h75
  text "B" at 14915,-4415 h75
  text "DWG NO" at 15265,-4415 h75
  text "DWG NO" at 15265,-4415 h75
  text "*********" at 15865,-4415 h75
  text "*********" at 15865,-4415 h75
  text "REV" at 17165,-4415 h75
  text "REV" at 17165,-4415 h75
  text "**" at 17465,-4415 h75
  text "**" at 17465,-4415 h75
  text "FRACTIONS +" at 10640,-4490 h75
  text "FRACTIONS +" at 10640,-4490 h75
  text "SCALE" at 14515,-4665 h75
  text "SCALE" at 14515,-4665 h75
  text "1:1" at 14915,-4665 h75
  text "1:1" at 14915,-4665 h75
  text "SHEET" at 16515,-4665 h75
  text "SHEET" at 16515,-4665 h75
  text "1 OF 1" at 17115,-4665 h75
  text "1 OF 1" at 17115,-4665 h75
LAY10:
  text "10" at 2635,-1790 h75
  text "10" at 2635,-1790 h75
  text "LAYER 10(INTERNAL SIGNAL)" at 2185,-1940 h60
  text "LAYER 10(INTERNAL SIGNAL)" at 2185,-1940 h60
LAY7:
  text "7" at 2685,-1790 h75
  text "7" at 2685,-1790 h75
  text "LAYER 7 (INTERNAL SIGNAL)" at 2185,-1940 h60
  text "LAYER 7 (INTERNAL SIGNAL)" at 2185,-1940 h60
LAY13:
  text "13" at 2635,-1790 h75
  text "13" at 2635,-1790 h75
  text "LAYER 13(GND PLANE)" at 2185,-1940 h60
  text "LAYER 13(GND PLANE)" at 2185,-1940 h60
LAY11:
  text "11" at 2635,-1790 h75
  text "11" at 2635,-1790 h75
  text "LAYER 11(GND PLANE)" at 2185,-1940 h60
  text "LAYER 11(GND PLANE)" at 2185,-1940 h60
LAY6:
  text "6" at 2685,-1790 h75
  text "6" at 2685,-1790 h75
  text "LAYER 6 (GND PLANE)" at 2185,-1940 h60
  text "LAYER 6 (GND PLANE)" at 2185,-1940 h60
LAY12:
  text "12" at 2635,-1790 h75
  text "12" at 2635,-1790 h75
  text "LAYER 12(INTERNAL SIGNAL)" at 2185,-1940 h60
  text "LAYER 12(INTERNAL SIGNAL)" at 2185,-1940 h60
LAY8:
  text "8" at 2685,-1790 h75
  text "8" at 2685,-1790 h75
  text "LAYER 8 (GND PLANE)" at 2185,-1940 h60
  text "LAYER 8 (GND PLANE)" at 2185,-1940 h60
LAY17:
  text "17" at 2635,-1790 h75
  text "17" at 2635,-1790 h75
  text "LAYER 17(GND PLANE)" at 2185,-1940 h60
  text "LAYER 17(GND PLANE)" at 2185,-1940 h60
LAY15:
  text "15" at 2635,-1790 h75
  text "15" at 2635,-1790 h75
  text "LAYER 15(GND PLANE)" at 2185,-1940 h60
  text "LAYER 15(GND PLANE)" at 2185,-1940 h60
LAY9:
  text "9" at 2685,-1790 h75
  text "9" at 2685,-1790 h75
  text "LAYER 9 (INTERNAL SIGNAL)" at 2185,-1940 h60
  text "LAYER 9 (INTERNAL SIGNAL)" at 2185,-1940 h60
DXF_0731:
  drawing of 196 lines, arcs and shapes, not listed
  text "Sofer Lib Information" at 641.31,2384.09 h25
  text "Ref PN: FRD154BP2902-CTP" at 671.31,2334.09 h25
  text "Creat : Ziv" at 671.31,2294.09 h25
  text "Date  : 2016-05-28" at 671.31,2254.09 h25
  text "Rev   : A1" at 671.31,2214.09 h25
  text "Remark: D031-023A1" at 671.31,2174.09 h25
  text "42.66" at 838.1,2062 h16
  text "31.52" at 838.1,2032 h16
  text "28.32" at 838.1,1997 h16
  text "10.71" at -251.9,1722 h16
  text "11.31" at 88.1,1627 h16
  text "33.72" at 123.1,1362 h16
  text "28.32" at 313.1,1352 h16
  text "NO" at 815.1,1285 h35
  text "U888" at 789.1,1245 h40
  text "15" at 1746.1,1060.98 h16
  text "9" at 2052.1,825.98 h16
  text "1" at 77.1,492 h16
  text "LCD_FRD154BP2902-CTP" at 623.1,445 h30
  text "Value" at 788.1,445 h30
  text "/XX" at 2635,-1790 h75
  text "14" at 2635,-1790 h75
  text "16" at 2635,-1790 h75
  text "/XX" at 2635,-1790 h75
  text "14" at 2635,-1790 h75
  text "16" at 2635,-1790 h75
  text "LAYER 14(INTERNAL SIGNAL)" at 2185,-1940 h60
  text "LAYER 16(INTERNAL SIGNAL)" at 2185,-1940 h60
  text "ASSEMBLY (PRIMARY)" at 2185,-1940 h60
  text "MUTI-PACK DRAWING" at 2185,-1940 h60
  text "LAYER 14(INTERNAL SIGNAL)" at 2185,-1940 h60
  text "LAYER 16(INTERNAL SIGNAL)" at 2185,-1940 h60
  text "ASSEMBLY (PRIMARY)" at 2185,-1940 h60
  text "MUTI-PACK DRAWING" at 2185,-1940 h60
  text "ASSEMBLY (SECONDARY)" at 3436,-1944 h60
  text "ASSEMBLY (SECONDARY)" at 3436,-1944 h60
